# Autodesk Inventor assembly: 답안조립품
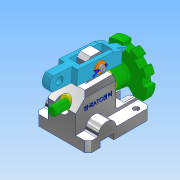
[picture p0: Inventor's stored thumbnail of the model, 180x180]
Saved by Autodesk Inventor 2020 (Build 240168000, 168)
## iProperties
Created: 2022-08
Part Number: 답안조립품
Document SubType Name: Assembly
Designer: user
Author: user
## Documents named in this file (8)
- C:\Users\user\Desktop\720806V1013\답안조립품.iam
- C:\Users\user\Desktop\720806V1013\본체.ipt
- C:\Users\user\Desktop\720806V1013\부시.ipt
- C:\Users\user\Desktop\720806V1013\분할대.ipt
- C:\Users\user\Desktop\720806V1013\분할축.ipt
- C:\Users\user\Desktop\720806V1013\분할핀.ipt
- C:\Users\user\Desktop\720806V1013\와셔.ipt
- C:\Users\user\Desktop\720806V1013\클레비스핀.ipt
